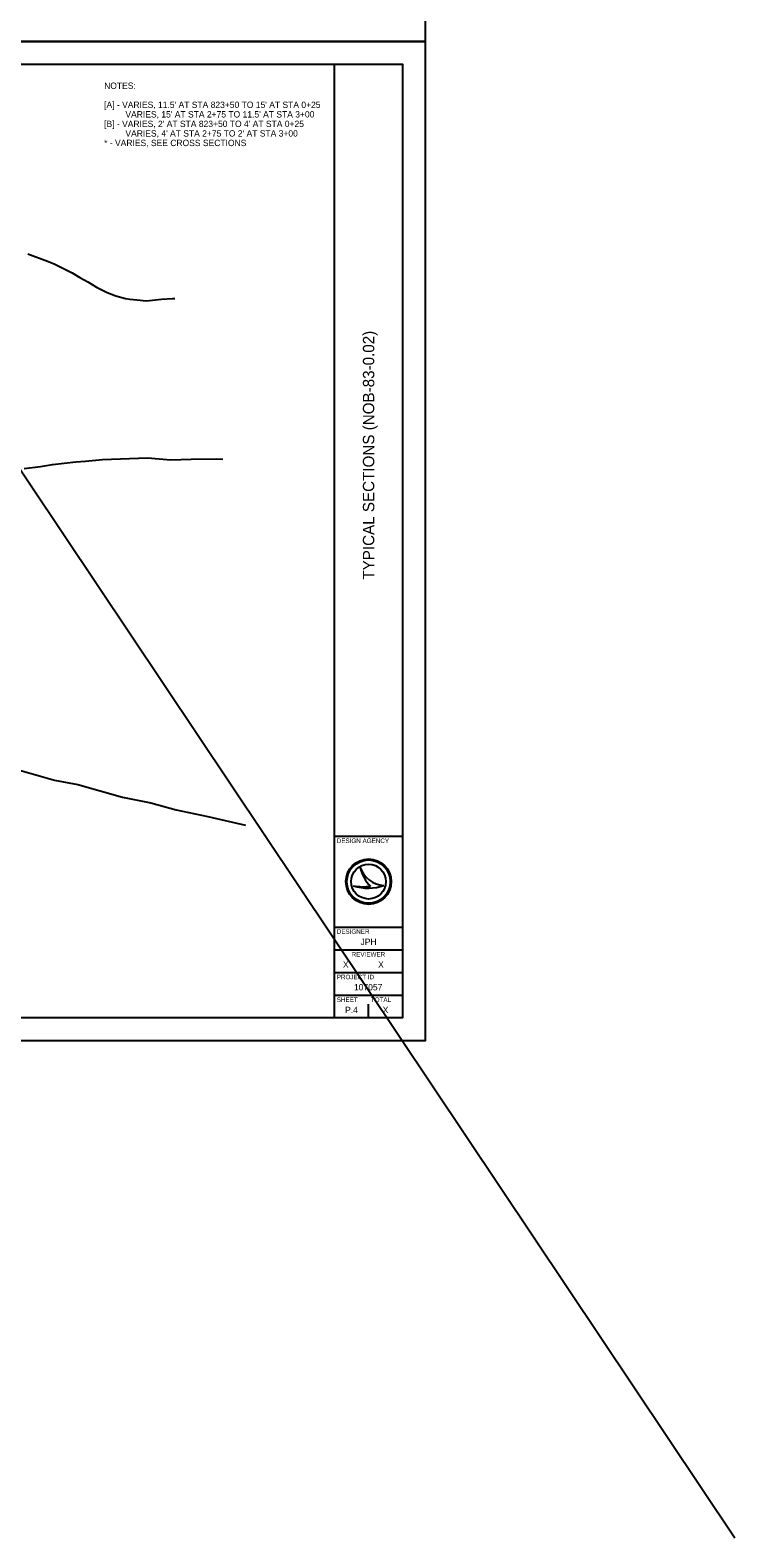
# Model space of a CAD drawing. Extents: x -345 to 102, y -108 to 100.
# Drawn here: x -259.3 to -212.7, y -108.1 to -8.5 of the extents above; entities that cross this region are included whole.
import ezdxf

# ---------------------------------------------------------------- set-up
doc = ezdxf.new("R2010")
doc.units = 0
for name, color, linetype in [('DT_X_Terrain_Ground_Line', 7, 'Continuous'), ('SH_Border', 7, 'Continuous'), ('SH_Cut_Line', 7, 'Continuous'), ('SH_Data', 7, 'Continuous'), ('TX_X_1', 7, 'Continuous'), ('XS_P_Finished_Grade', 7, 'Continuous')]:
    doc.layers.add(name, color=color, linetype=linetype)

msp = doc.modelspace()

# ---------------------------------------------------------------- linework, layer by layer
at = {"layer": 'DT_X_Terrain_Ground_Line'}
for points in [[(-259.409, -23.227), (-258.098, -23.707), (-257.671, -23.898), (-256.82, -24.307), (-256.477, -24.494), (-255.964, -24.785), (-255.448, -25.086), (-254.864, -25.44), (-254.603, -25.565), (-254.157, -25.775), (-253.585, -25.993), (-252.955, -26.173), (-252.671, -26.215), (-252.194, -26.258), (-251.555, -26.325), (-250.565, -26.218), (-249.858, -26.175), (-249.687, -26.17)], [(-259.654, -37.404), (-258.574, -37.286), (-257.767, -37.142), (-256.227, -36.975), (-255.586, -36.926), (-254.464, -36.823), (-251.504, -36.714), (-249.953, -36.834), (-248.621, -36.799), (-246.929, -36.76), (-246.529, -36.795)], [(-257.648, -57.997), (-256.102, -58.293), (-253.155, -59.12), (-251.286, -59.494), (-249.612, -59.965), (-247.507, -60.4), (-245.016, -60.981)]]:
    msp.add_lwpolyline(points, dxfattribs=at)
at = {"layer": 'SH_Border'}
for p, q in [((-239.144, -73.702), (-239.144, -10.702)), ((-239.144, -61.702), (-234.644, -61.702)), ((-239.144, -67.702), (-234.644, -67.702)), ((-239.144, -69.202), (-234.644, -69.202)), ((-239.144, -70.702), (-234.644, -70.702)), ((-239.144, -72.202), (-234.644, -72.202))]:
    msp.add_line(p, q, dxfattribs=at)
msp.add_lwpolyline([(-330.644, -10.702), (-234.644, -10.702), (-234.644, -73.702), (-330.644, -73.702)], close=True, dxfattribs=at)
at = {"layer": 'SH_Cut_Line'}
for points in [[(-335.144, -9.202), (-233.144, -9.202), (-233.144, 56.798), (-335.144, 56.798)], [(-335.144, -75.202), (-233.144, -75.202), (-233.144, -9.202), (-335.144, -9.202)]]:
    msp.add_lwpolyline(points, close=True, dxfattribs=at)
at = {"layer": 'SH_Data'}
for p, q in [((-237.442, -63.773), (-237.442, -63.773)), ((-236.894, -64.702), (-236.894, -64.702)), ((-237.893, -64.973), (-237.893, -64.973)), ((-235.882, -64.946), (-235.882, -64.946)), ((-238.019, -73.177), (-238.019, -73.177)), ((-236.894, -73.702), (-236.894, -72.802))]:
    msp.add_line(p, q, dxfattribs=at)
for radius in [1.5, 1.43, 1.43, 1.147]:
    msp.add_circle((-236.894, -64.702), radius, dxfattribs=at)
for centre, radius, start, end in [((-235.796, -63.209), 1.74, 198.92567, 198.93195), ((-235.104, -63.292), 2.387, 191.63793, 191.64215), ((-235.796, -63.209), 1.74, 198.93195, 267.16574), ((-235.104, -63.292), 2.387, 191.64215, 226.09467), ((-237.2, -61.239), 3.798, 259.49639, 259.49952), ((-236.926, -62.092), 3.039, 251.45274, 251.45764), ((-236.926, -62.092), 3.039, 251.45764, 290.08324), ((-237.2, -61.239), 3.798, 259.49952, 276.66723)]:
    msp.add_arc(centre, radius, start, end, dxfattribs=at)
at = {"layer": 'TX_X_1'}
msp.add_line((-344.901, 89.556), (-212.699, -108.052), dxfattribs=at)
at = {"layer": 'XS_P_Finished_Grade'}
msp.add_line((-264.963, -55.907), (-257.648, -57.997), dxfattribs=at)

# ---------------------------------------------------------------- texts
at = {"layer": 'SH_Data'}
msp.add_text('TYPICAL SECTIONS (NOB-83-0.02)', height=0.75, rotation=90, dxfattribs=at).set_placement((-236.519, -44.752))
for s, height, p in [('DESIGN AGENCY', 0.3, (-238.994, -62.152)), ('DESIGNER', 0.3, (-238.994, -68.152)), ('JPH', 0.42, (-237.425, -68.887)), ('REVIEWER', 0.3, (-238.009, -69.652)), ('X', 0.42, (-238.588, -70.387)), ('X', 0.42, (-236.263, -70.387)), ('PROJECT ID', 0.3, (-238.994, -71.152)), ('107057', 0.42, (-237.859, -71.887)), ('SHEET', 0.3, (-238.994, -72.652)), ('TOTAL', 0.3, (-236.744, -72.652)), ('P.4', 0.42, (-238.445, -73.387)), ('X', 0.42, (-235.963, -73.387))]:
    msp.add_text(s, height=height, dxfattribs=at).set_placement(p)
at = {"layer": 'TX_X_1'}
for s, p in [('NOTES:', (-254.362, -12.332)), ("[A] - VARIES, 11.5' AT STA 823+50 TO 15' AT STA 0+25", (-254.362, -13.592)), ("         VARIES, 15' AT STA 2+75 TO 11.5' AT STA 3+00", (-254.362, -14.222)), ("[B] - VARIES, 2' AT STA 823+50 TO 4' AT STA 0+25", (-254.362, -14.852)), ('* - VARIES, SEE CROSS SECTIONS', (-254.362, -16.112)), ("         VARIES, 4' AT STA 2+75 TO 2' AT STA 3+00", (-254.362, -15.482))]:
    msp.add_text(s, height=0.42, dxfattribs=at).set_placement(p)

doc.saveas('drawing.dxf')
